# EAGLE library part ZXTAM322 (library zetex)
15V NPN LOW SATURATION TRANSISTOR MPPS Miniature Package Power Solutions Source: www.zetex.com/ .. zxtam322.pdf
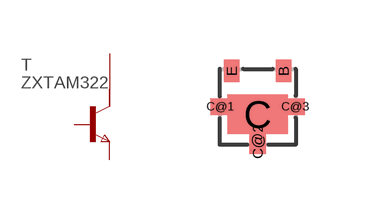
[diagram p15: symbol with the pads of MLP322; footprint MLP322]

Designator prefix T

## ZXTAM322 (OC_FARNELL: unknown; OC_NEWARK: unknown)  [MLP322]
B  B  pas
C  C1  pas
C@1  C2  pas
C@2  C3  pas
C@3  C4  pas
E  E  pas

## Footprint MLP322 (pad centres in mm)
MLP322 Package Source: www.zetex.com/ .. zxtam322.pdf
smd 0.38 x 0.55: B 0.65,0.9; E -0.65,0.9
smd 1.52 x 0.99: C 0,-0.188
smd 0.475 x 0.4: C@1 -0.938,0; C@3 0.938,0
smd 0.4 x 0.6: C@2 0,-0.875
